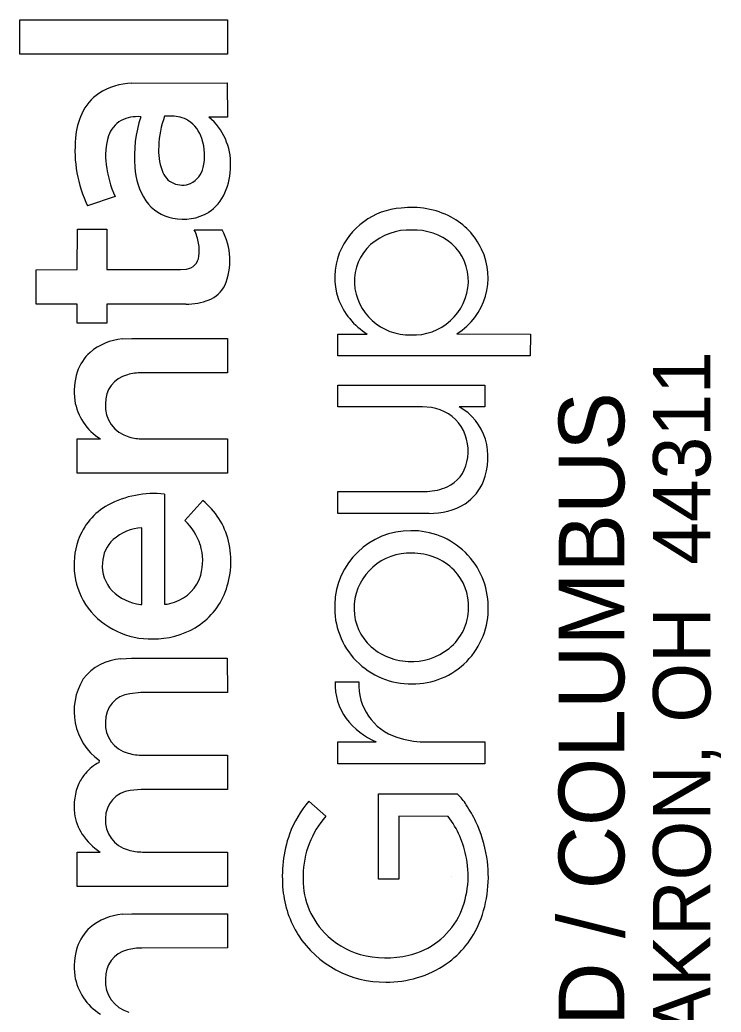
# Model space of a CAD drawing. Extents: x 0 to 34, y 0 to 22.
# Drawn here: x 32.376 to 32.984, y 3.882 to 4.744 of the extents above; entities that cross this region are included whole.
import ezdxf

# ---------------------------------------------------------------- set-up
doc = ezdxf.new("R2010")
doc.units = 0
doc.layers.add('SH_Data', color=7, linetype='Continuous')

msp = doc.modelspace()

# ---------------------------------------------------------------- linework, layer by layer
at = {"layer": 'SH_Data'}
for p, q in [((32.37557, 4.71411), (32.37557, 4.74397)), ((32.37557, 4.74397), (32.55571, 4.74397)), ((32.55571, 4.74397), (32.55571, 4.71411)), ((32.55571, 4.71411), (32.37557, 4.71411)), ((32.47265, 4.68899), (32.55553, 4.68918)), ((32.55553, 4.68918), (32.55571, 4.65956)), ((32.55571, 4.65956), (32.53971, 4.65956)), ((32.45818, 4.59045), (32.43431, 4.58233)), ((32.42542, 4.52705), (32.42548, 4.56209)), ((32.42548, 4.56209), (32.45108, 4.56209)), ((32.45108, 4.56209), (32.45117, 4.52705)), ((32.52695, 4.56159), (32.5511, 4.56159)), ((32.38964, 4.52701), (32.42542, 4.52705)), ((32.38964, 4.49719), (32.38964, 4.52701)), ((32.45117, 4.52705), (32.51498, 4.52705)), ((32.51498, 4.52705), (32.52005, 4.52749)), ((32.42542, 4.49717), (32.38964, 4.49719)), ((32.42542, 4.48067), (32.42542, 4.49717)), ((32.51969, 4.49718), (32.45108, 4.49715)), ((32.45108, 4.49715), (32.45108, 4.48066)), ((32.45108, 4.48066), (32.42542, 4.48067)), ((32.46439, 4.46686), (32.47289, 4.46732)), ((32.47289, 4.46732), (32.55571, 4.46732)), ((32.55571, 4.46732), (32.55571, 4.43753)), ((32.65152, 4.47113), (32.67709, 4.47115)), ((32.65152, 4.45215), (32.65152, 4.47113)), ((32.75491, 4.47132), (32.81858, 4.47108)), ((32.81858, 4.47108), (32.81843, 4.45215)), ((32.81843, 4.45215), (32.65152, 4.45215)), ((32.55571, 4.43753), (32.4814, 4.43746)), ((32.65152, 4.40801), (32.65153, 4.42672)), ((32.65153, 4.42672), (32.7791, 4.42664)), ((32.7791, 4.42664), (32.77908, 4.40796)), ((32.7249, 4.40796), (32.65152, 4.40801)), ((32.7328, 4.40727), (32.7249, 4.40796)), ((32.77908, 4.40796), (32.75689, 4.40796)), ((32.42542, 4.38016), (32.44552, 4.38021)), ((32.42542, 4.35035), (32.42542, 4.38016)), ((32.48222, 4.38021), (32.55569, 4.38021)), ((32.55569, 4.38021), (32.55571, 4.35045)), ((32.55571, 4.35045), (32.42542, 4.35035)), ((32.65154, 4.33443), (32.72905, 4.3345)), ((32.65165, 4.31543), (32.65154, 4.33443)), ((32.50108, 4.33209), (32.50118, 4.23657)), ((32.51882, 4.30927), (32.53422, 4.32662)), ((32.73073, 4.31543), (32.65165, 4.31543)), ((32.48144, 4.23644), (32.48144, 4.30296)), ((32.48016, 4.23628), (32.48144, 4.23644)), ((32.46329, 4.18915), (32.47259, 4.18968)), ((32.47259, 4.18968), (32.55557, 4.18968)), ((32.55557, 4.18968), (32.55571, 4.15982)), ((32.64932, 4.16907), (32.66978, 4.16907)), ((32.48058, 4.15981), (32.47102, 4.15881)), ((32.55571, 4.15982), (32.48058, 4.15981)), ((32.65152, 4.11699), (32.68476, 4.117)), ((32.65152, 4.098), (32.65152, 4.11699)), ((32.72605, 4.11703), (32.7791, 4.11696)), ((32.7791, 4.11696), (32.77903, 4.098)), ((32.48218, 4.10553), (32.55571, 4.10548)), ((32.55571, 4.10548), (32.55571, 4.07568)), ((32.44443, 4.09922), (32.44455, 4.10072)), ((32.77903, 4.098), (32.65152, 4.098)), ((32.4809, 4.07567), (32.47143, 4.07474)), ((32.55571, 4.07568), (32.4809, 4.07567)), ((32.6868, 4.07185), (32.75516, 4.07192)), ((32.6868, 3.99778), (32.6868, 4.07185)), ((32.62636, 4.06548), (32.64114, 4.05241)), ((32.70448, 4.05241), (32.70432, 3.99775)), ((32.74737, 4.05227), (32.70448, 4.05241)), ((32.42542, 3.99152), (32.42545, 4.02138)), ((32.42545, 4.02138), (32.44515, 4.02138)), ((32.48206, 4.02138), (32.55571, 4.02136)), ((32.55571, 4.02136), (32.55571, 3.99156)), ((32.75, 4), (32.75, 4)), ((32.55571, 3.99156), (32.42542, 3.99152)), ((32.70432, 3.99775), (32.6868, 3.99778)), ((32.46439, 3.96736), (32.47289, 3.96783)), ((32.47289, 3.96783), (32.55571, 3.96783)), ((32.55571, 3.96783), (32.55571, 3.93804)), ((32.55571, 3.93804), (32.4814, 3.93796))]:
    msp.add_line(p, q, dxfattribs=at)
msp.add_lwpolyline([(32.37557, 4.71411), (32.37557, 4.74397), (32.55571, 4.74397), (32.55571, 4.71411)], close=True, dxfattribs=at)
for points in [[(32.47265, 4.68899), (32.55553, 4.68918), (32.55571, 4.65956)], [(32.55571, 4.65956), (32.53971, 4.65956)], [(32.45818, 4.59045), (32.43431, 4.58233)], [(32.51969, 4.49718), (32.45108, 4.49715), (32.45108, 4.48066), (32.42542, 4.48067), (32.42542, 4.49717), (32.38964, 4.49719), (32.38964, 4.52701), (32.42542, 4.52705), (32.42548, 4.56209), (32.45108, 4.56209), (32.45117, 4.52705), (32.51498, 4.52705), (32.52005, 4.52749)], [(32.52695, 4.56159), (32.5511, 4.56159)], [(32.46439, 4.46686), (32.47289, 4.46732), (32.55571, 4.46732), (32.55571, 4.43753), (32.4814, 4.43746)], [(32.75491, 4.47132), (32.81858, 4.47108), (32.81843, 4.45215), (32.65152, 4.45215)], [(32.65152, 4.45215), (32.65152, 4.47113), (32.67709, 4.47115)], [(32.7328, 4.40727), (32.7249, 4.40796), (32.65152, 4.40801), (32.65153, 4.42672), (32.7791, 4.42664), (32.77908, 4.40796), (32.75689, 4.40796)], [(32.42542, 4.35035), (32.42542, 4.38016), (32.44552, 4.38021)], [(32.48222, 4.38021), (32.55569, 4.38021), (32.55571, 4.35045), (32.42542, 4.35035)], [(32.73073, 4.31543), (32.65165, 4.31543), (32.65154, 4.33443), (32.72905, 4.3345)], [(32.50108, 4.33209), (32.50118, 4.23657)], [(32.51882, 4.30927), (32.53422, 4.32662)], [(32.48016, 4.23628), (32.48144, 4.23644), (32.48144, 4.30296)], [(32.46329, 4.18915), (32.47259, 4.18968), (32.55557, 4.18968), (32.55571, 4.15982), (32.48058, 4.15981), (32.47102, 4.15881)], [(32.64932, 4.16907), (32.66978, 4.16907)], [(32.72605, 4.11703), (32.7791, 4.11696), (32.77903, 4.098), (32.65152, 4.098)], [(32.65152, 4.098), (32.65152, 4.11699), (32.68476, 4.117)], [(32.48218, 4.10553), (32.55571, 4.10548), (32.55571, 4.07568), (32.4809, 4.07567), (32.47143, 4.07474)], [(32.44443, 4.09922), (32.44455, 4.10072)], [(32.74737, 4.05227), (32.70448, 4.05241), (32.70432, 3.99775), (32.6868, 3.99778), (32.6868, 4.07185), (32.75516, 4.07192)], [(32.62636, 4.06548), (32.64114, 4.05241)], [(32.42542, 3.99152), (32.42545, 4.02138), (32.44515, 4.02138)], [(32.48206, 4.02138), (32.55571, 4.02136), (32.55571, 3.99156), (32.42542, 3.99152)], [(32.46439, 3.96736), (32.47289, 3.96783), (32.55571, 3.96783), (32.55571, 3.93804), (32.4814, 3.93796)]]:
    msp.add_lwpolyline(points, dxfattribs=at)
for centre, radius, start, end in [((32.47452, 4.63256), 0.05646, 91.89422, 122.63175), ((32.47452, 4.63256), 0.05646, 91.89422, 122.63175), ((32.46847, 4.64467), 0.04302, 124.53704, 155.65938), ((32.46847, 4.64467), 0.04302, 124.53704, 155.65938), ((32.48824, 4.63612), 0.06457, 155.9764, 175.31491), ((32.48824, 4.63612), 0.06457, 155.9764, 175.31491), ((32.47525, 4.6356), 0.024, 119.42515, 161.66285), ((32.47525, 4.6356), 0.024, 119.42515, 161.66285), ((32.47786, 4.62778), 0.03213, 85.38017, 116.62224), ((32.47786, 4.62778), 0.03213, 85.38017, 116.62224), ((32.58787, 4.62508), 0.1129, 162.08213, 184.52847), ((32.58787, 4.62508), 0.1129, 162.08213, 184.52847), ((32.58013, 4.63131), 0.08411, 159.83657, 178.03621), ((32.58013, 4.63131), 0.08411, 159.83657, 178.03621), ((32.50509, 4.60743), 0.05302, 79.66963, 94.23216), ((32.50509, 4.60743), 0.05302, 79.66963, 94.23216), ((32.50892, 4.63643), 0.02384, 56.89129, 76.21489), ((32.50892, 4.63643), 0.02384, 56.89129, 76.21489), ((32.5052, 4.63184), 0.02973, 17.59837, 55.72819), ((32.5052, 4.63184), 0.02973, 17.59837, 55.72819), ((32.50551, 4.61914), 0.05295, 358.07459, 49.76196), ((32.50551, 4.61914), 0.05295, 358.07459, 49.76196), ((32.53639, 4.63078), 0.113, 174.61011, 205.38987), ((32.53639, 4.63078), 0.113, 174.61011, 205.38987), ((32.50758, 4.62645), 0.05758, 163.13694, 188.16749), ((32.50758, 4.62645), 0.05758, 163.13694, 188.16749), ((32.4916, 4.6264), 0.04435, 345.94084, 18.99188), ((32.4916, 4.6264), 0.04435, 345.94084, 18.99188), ((32.54655, 4.6303), 0.05063, 175.59026, 199.88569), ((32.54655, 4.6303), 0.05063, 175.59026, 199.88569), ((32.54725, 4.62973), 0.09735, 186.75982, 203.79807), ((32.54725, 4.62973), 0.09735, 186.75982, 203.79807), ((32.53279, 4.61874), 0.05752, 182.56764, 213.71437), ((32.53279, 4.61874), 0.05752, 182.56764, 213.71437), ((32.51642, 4.61886), 0.01841, 198.28436, 293.30806), ((32.51642, 4.61886), 0.01841, 198.28436, 293.30806), ((32.51521, 4.61994), 0.01989, 295.28829, 347.46387), ((32.51521, 4.61994), 0.01989, 295.28829, 347.46387), ((32.50187, 4.61678), 0.05657, 336.01604, 0.59505), ((32.50187, 4.61678), 0.05657, 336.01604, 0.59505), ((32.51752, 4.60969), 0.03938, 303.44357, 336.18), ((32.51752, 4.60969), 0.03938, 303.44357, 336.18), ((32.51487, 4.60782), 0.03656, 215.06685, 259.81327), ((32.51487, 4.60782), 0.03656, 215.06685, 259.81327), ((32.51753, 4.6131), 0.04227, 257.52557, 300.88195), ((32.51753, 4.6131), 0.04227, 257.52557, 300.88195), ((32.71081, 4.51825), 0.06243, 93.98662, 158.31194), ((32.71081, 4.51825), 0.06243, 93.98662, 158.31194), ((32.71557, 4.5065), 0.07459, 62.68889, 97.01346), ((32.71557, 4.5065), 0.07459, 62.68889, 97.01346), ((32.72123, 4.51914), 0.06076, 25.06574, 61.96022), ((32.72123, 4.51914), 0.06076, 25.06574, 61.96022), ((32.48625, 4.54199), 0.04518, 10.15449, 25.72303), ((32.48625, 4.54199), 0.04518, 10.15449, 25.72303), ((32.50302, 4.53506), 0.05491, 336.58903, 28.89913), ((32.50302, 4.53506), 0.05491, 336.58903, 28.89913), ((32.71379, 4.51017), 0.05134, 87.89653, 131.18123), ((32.71379, 4.51017), 0.05134, 87.89653, 131.18123), ((32.7175, 4.51023), 0.05127, 49.90886, 92.03625), ((32.7175, 4.51023), 0.05127, 49.90886, 92.03625), ((32.49573, 4.54365), 0.03556, 351.91398, 10.20594), ((32.49573, 4.54365), 0.03556, 351.91398, 10.20594), ((32.70695, 4.52016), 0.05815, 158.65601, 198.17101), ((32.70695, 4.52016), 0.05815, 158.65601, 198.17101), ((32.7092, 4.51674), 0.04338, 132.32887, 182.09489), ((32.7092, 4.51674), 0.04338, 132.32887, 182.09489), ((32.72154, 4.51733), 0.04327, 358.04871, 47.94467), ((32.72154, 4.51733), 0.04327, 358.04871, 47.94467), ((32.7245, 4.52004), 0.05743, 301.97764, 25.64176), ((32.7245, 4.52004), 0.05743, 301.97764, 25.64176), ((32.51837, 4.54001), 0.01263, 277.61423, 353.79181), ((32.51837, 4.54001), 0.01263, 277.61423, 353.79181), ((32.71352, 4.51815), 0.04776, 183.59741, 271.7045), ((32.71352, 4.51815), 0.04776, 183.59741, 271.7045), ((32.71717, 4.51801), 0.04766, 267.31494, 357.4019), ((32.71717, 4.51801), 0.04766, 267.31494, 357.4019), ((32.52913, 4.52612), 0.02749, 292.68889, 332.05977), ((32.52913, 4.52612), 0.02749, 292.68889, 332.05977), ((32.52088, 4.54856), 0.05139, 268.67266, 291.52354), ((32.52088, 4.54856), 0.05139, 268.67266, 291.52354), ((32.7103, 4.52433), 0.0627, 200.83985, 238.01619), ((32.7103, 4.52433), 0.0627, 200.83985, 238.01619), ((32.46871, 4.41716), 0.04988, 94.97056, 130.22484), ((32.46871, 4.41716), 0.04988, 94.97056, 130.22484), ((32.46348, 4.42551), 0.04016, 132.22383, 161.68229), ((32.46348, 4.42551), 0.04016, 132.22383, 161.68229), ((32.47872, 4.42108), 0.05602, 162.27398, 187.79173), ((32.47872, 4.42108), 0.05602, 162.27398, 187.79173), ((32.48108, 4.39145), 0.04601, 89.60515, 105.33026), ((32.48108, 4.39145), 0.04601, 89.60515, 105.33026), ((32.47482, 4.41155), 0.02498, 103.68683, 182.21395), ((32.47482, 4.41155), 0.02498, 103.68683, 182.21395), ((32.47027, 4.4209), 0.04763, 188.96462, 238.69865), ((32.47027, 4.4209), 0.04763, 188.96462, 238.69865), ((32.47735, 4.40846), 0.02757, 175.58441, 255.13816), ((32.47735, 4.40846), 0.02757, 175.58441, 255.13816), ((32.72711, 4.36998), 0.03772, 33.50082, 81.32954), ((32.72711, 4.36998), 0.03772, 33.50082, 81.32954), ((32.73239, 4.36485), 0.04959, 17.62209, 60.38974), ((32.73239, 4.36485), 0.04959, 17.62209, 60.38974), ((32.72414, 4.3695), 0.04048, 346.56179, 31.75389), ((32.72414, 4.3695), 0.04048, 346.56179, 31.75389), ((32.48183, 4.42235), 0.04215, 254.08913, 270.52838), ((32.48183, 4.42235), 0.04215, 254.08913, 270.52838), ((32.72343, 4.36415), 0.05838, 339.16197, 15.61485), ((32.72343, 4.36415), 0.05838, 339.16197, 15.61485), ((32.73371, 4.36616), 0.03042, 294.63214, 348.48625), ((32.73371, 4.36616), 0.03042, 294.63214, 348.48625), ((32.739, 4.35901), 0.04201, 303.10391, 338.15613), ((32.739, 4.35901), 0.04201, 303.10391, 338.15613), ((32.72747, 4.38081), 0.04633, 271.95199, 294.08943), ((32.72747, 4.38081), 0.04633, 271.95199, 294.08943), ((32.49176, 4.24874), 0.08387, 83.62118, 118.28448), ((32.49176, 4.24874), 0.08387, 83.62118, 118.28448), ((32.49399, 4.2763), 0.06443, 13.53275, 51.36266), ((32.49399, 4.2763), 0.06443, 13.53275, 51.36266), ((32.47894, 4.27368), 0.05583, 118.82935, 160.62242), ((32.47894, 4.27368), 0.05583, 118.82935, 160.62242), ((32.7321, 4.37256), 0.05715, 268.62699, 301.47779), ((32.7321, 4.37256), 0.05715, 268.62699, 301.47779), ((32.48033, 4.27018), 0.05485, 19.0387, 45.44322), ((32.48033, 4.27018), 0.05485, 19.0387, 45.44322), ((32.4844, 4.26071), 0.04236, 94.01311, 130.88062), ((32.4844, 4.26071), 0.04236, 94.01311, 130.88062), ((32.71435, 4.23484), 0.06552, 89.48213, 178.77752), ((32.71435, 4.23484), 0.06552, 89.48213, 178.77752), ((32.71582, 4.23414), 0.06623, 0.42265, 90.7613), ((32.71582, 4.23414), 0.06623, 0.42265, 90.7613), ((32.48697, 4.27074), 0.06438, 160.52138, 215.78155), ((32.48697, 4.27074), 0.06438, 160.52138, 215.78155), ((32.47703, 4.2709), 0.02985, 132.98553, 177.1802), ((32.47703, 4.2709), 0.02985, 132.98553, 177.1802), ((32.48289, 4.27384), 0.0758, 339.35431, 13.37708), ((32.48289, 4.27384), 0.0758, 339.35431, 13.37708), ((32.48724, 4.27433), 0.04701, 344.60723, 17.00675), ((32.48724, 4.27433), 0.04701, 344.60723, 17.00675), ((32.71397, 4.23244), 0.04846, 87.68827, 175.01696), ((32.71397, 4.23244), 0.04846, 87.68827, 175.01696), ((32.71659, 4.23036), 0.05052, 44.91202, 90.75914), ((32.71659, 4.23036), 0.05052, 44.91202, 90.75914), ((32.47824, 4.26966), 0.03114, 175.00138, 223.2876), ((32.47824, 4.26966), 0.03114, 175.00138, 223.2876), ((32.71955, 4.23452), 0.04549, 358.32279, 43.83486), ((32.71955, 4.23452), 0.04549, 358.32279, 43.83486), ((32.49895, 4.27177), 0.03504, 288.01084, 343.55364), ((32.49895, 4.27177), 0.03504, 288.01084, 343.55364), ((32.48546, 4.27826), 0.04232, 225.06454, 262.79701), ((32.48546, 4.27826), 0.04232, 225.06454, 262.79701), ((32.49548, 4.26982), 0.0626, 300.94393, 338.73223), ((32.49548, 4.26982), 0.0626, 300.94393, 338.73223), ((32.48908, 4.27516), 0.06872, 217.74341, 271.65606), ((32.48908, 4.27516), 0.06872, 217.74341, 271.65606), ((32.50129, 4.25678), 0.02021, 269.70042, 294.87295), ((32.50129, 4.25678), 0.02021, 269.70042, 294.87295), ((32.71483, 4.2334), 0.06606, 177.53728, 270.94524), ((32.71483, 4.2334), 0.06606, 177.53728, 270.94524), ((32.71085, 4.23311), 0.0453, 175.51467, 221.42047), ((32.71085, 4.23311), 0.0453, 175.51467, 221.42047), ((32.71671, 4.23271), 0.06536, 269.30834, 1.67905), ((32.71671, 4.23271), 0.06536, 269.30834, 1.67905), ((32.71931, 4.23374), 0.04572, 308.90382, 359.30947), ((32.71931, 4.23374), 0.04572, 308.90382, 359.30947), ((32.49204, 4.27702), 0.07055, 269.20529, 300.33566), ((32.49204, 4.27702), 0.07055, 269.20529, 300.33566), ((32.71399, 4.23734), 0.05046, 222.66255, 268.37331), ((32.71399, 4.23734), 0.05046, 222.66255, 268.37331), ((32.71567, 4.23859), 0.05178, 266.55312, 308.67253), ((32.71567, 4.23859), 0.05178, 266.55312, 308.67253), ((32.46638, 4.14404), 0.04521, 93.91118, 142.30723), ((32.46638, 4.14404), 0.04521, 93.91118, 142.30723), ((32.47585, 4.14373), 0.05319, 148.28793, 233.9556), ((32.47585, 4.14373), 0.05319, 148.28793, 233.9556), ((32.69878, 4.16662), 0.04952, 177.16211, 216.28024), ((32.69878, 4.16662), 0.04952, 177.16211, 216.28024), ((32.71735, 4.16638), 0.04764, 176.76988, 252.15044), ((32.71735, 4.16638), 0.04764, 176.76988, 252.15044), ((32.47384, 4.13499), 0.02399, 96.75763, 181.6251), ((32.47384, 4.13499), 0.02399, 96.75763, 181.6251), ((32.70975, 4.17555), 0.06366, 216.91526, 246.88619), ((32.70975, 4.17555), 0.06366, 216.91526, 246.88619), ((32.47577, 4.13241), 0.02597, 175.81573, 256.16716), ((32.47577, 4.13241), 0.02597, 175.81573, 256.16716), ((32.7269, 4.19175), 0.07473, 251.13884, 269.34694), ((32.7269, 4.19175), 0.07473, 251.13884, 269.34694), ((32.4817, 4.15053), 0.04501, 254.34629, 270.61033), ((32.4817, 4.15053), 0.04501, 254.34629, 270.61033), ((32.4638, 4.06267), 0.04137, 117.91625, 139.24296), ((32.4638, 4.06267), 0.04137, 117.91625, 139.24296), ((32.46194, 4.06452), 0.03875, 139.52447, 154.84698), ((32.46194, 4.06452), 0.03875, 139.52447, 154.84698), ((32.47144, 4.0612), 0.04877, 156.06382, 187.3493), ((32.47144, 4.0612), 0.04877, 156.06382, 187.3493), ((32.47421, 4.05056), 0.02434, 96.5532, 179.94902), ((32.47421, 4.05056), 0.02434, 96.5532, 179.94902), ((32.72498, 4.03937), 0.04438, 30.98913, 47.16099), ((32.72498, 4.03937), 0.04438, 30.98913, 47.16099), ((32.70163, 4.00187), 0.09855, 139.79476, 159.13696), ((32.70163, 4.00187), 0.09855, 139.79476, 159.13696), ((32.67091, 4.00018), 0.11106, 25.30315, 33.96179), ((32.67091, 4.00018), 0.11106, 25.30315, 33.96179), ((32.46461, 4.05974), 0.04181, 186.5579, 213.38846), ((32.46461, 4.05974), 0.04181, 186.5579, 213.38846), ((32.47608, 4.04863), 0.02628, 175.722, 255.78627), ((32.47608, 4.04863), 0.02628, 175.722, 255.78627), ((32.69899, 4.00079), 0.07753, 138.25804, 179.70064), ((32.69899, 4.00079), 0.07753, 138.25804, 179.70064), ((32.67889, 4.00099), 0.08556, 10.07509, 36.83189), ((32.67889, 4.00099), 0.08556, 10.07509, 36.83189), ((32.6704, 3.99987), 0.11166, 8.80339, 25.33484), ((32.6704, 3.99987), 0.11166, 8.80339, 25.33484), ((32.47886, 4.07078), 0.0598, 214.70433, 235.68724), ((32.47886, 4.07078), 0.0598, 214.70433, 235.68724), ((32.7187, 3.99968), 0.11536, 161.14379, 185.62812), ((32.7187, 3.99968), 0.11536, 161.14379, 185.62812), ((32.48195, 4.06518), 0.0438, 253.66719, 270.14979), ((32.48195, 4.06518), 0.0438, 253.66719, 270.14979), ((32.68425, 4.00057), 0.08036, 333.46689, 11.03668), ((32.68425, 4.00057), 0.08036, 333.46689, 11.03668), ((32.67564, 3.99977), 0.10649, 338.28866, 9.28548), ((32.67564, 3.99977), 0.10649, 338.28866, 9.28548), ((32.68811, 3.99732), 0.06676, 176.66577, 223.6912), ((32.68811, 3.99732), 0.06676, 176.66577, 223.6912), ((32.69336, 3.99699), 0.08987, 185.50773, 212.01294), ((32.69336, 3.99699), 0.08987, 185.50773, 212.01294), ((32.46871, 3.91767), 0.04988, 94.97056, 130.22484), ((32.46871, 3.91767), 0.04988, 94.97056, 130.22484), ((32.69868, 3.99547), 0.0652, 282.88151, 331.81475), ((32.69868, 3.99547), 0.0652, 282.88151, 331.81475), ((32.46348, 3.92602), 0.04016, 132.22383, 161.68229), ((32.46348, 3.92602), 0.04016, 132.22383, 161.68229), ((32.69835, 3.99168), 0.08241, 305.03061, 337.67573), ((32.69835, 3.99168), 0.08241, 305.03061, 337.67573), ((32.69211, 3.99748), 0.08908, 212.70222, 270.71399), ((32.69211, 3.99748), 0.08908, 212.70222, 270.71399), ((32.69045, 4.00011), 0.07039, 224.02147, 253.88), ((32.69045, 4.00011), 0.07039, 224.02147, 253.88), ((32.47872, 3.92158), 0.05602, 162.27398, 187.79173), ((32.47872, 3.92158), 0.05602, 162.27398, 187.79173), ((32.48108, 3.89196), 0.04601, 89.60515, 105.33026), ((32.48108, 3.89196), 0.04601, 89.60515, 105.33026), ((32.47482, 3.91206), 0.02498, 103.68683, 182.21395), ((32.47482, 3.91206), 0.02498, 103.68683, 182.21395), ((32.69318, 4.01254), 0.08309, 254.45353, 283.9512), ((32.69318, 4.01254), 0.08309, 254.45353, 283.9512), ((32.69429, 3.99979), 0.09138, 269.3273, 304.19632), ((32.69429, 3.99979), 0.09138, 269.3273, 304.19632), ((32.47027, 3.92141), 0.04763, 188.96462, 238.69865), ((32.47027, 3.92141), 0.04763, 188.96462, 238.69865), ((32.47735, 3.90897), 0.02757, 175.58441, 255.13816), ((32.47735, 3.90897), 0.02757, 175.58441, 255.13816)]:
    msp.add_arc(centre, radius, start, end, dxfattribs=at)

# ---------------------------------------------------------------- texts
for s, height, p in [('450 GRANT ST., AKRON, OH  44311', 0.0498462, (32.97489, 3.33738)), ('AKRON / CLEVELAND / COLUMBUS', 0.056969, (32.90012, 3.138))]:
    msp.add_text(s, height=height, rotation=90, dxfattribs=at).set_placement(p)

doc.saveas('drawing.dxf')
